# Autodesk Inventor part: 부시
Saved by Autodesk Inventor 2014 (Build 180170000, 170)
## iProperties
Created: 2026-09
Part Number: 부시
Material: 일반
Document SubType Name: Modeling
Designer: dg
Density: 1 g/cm^3
Appearance: 기본값
Author: dg
Author: jhkim
Creation Date: 2026-08-27
Sending System: Autodesk Inventor 2027
Preprocessor: ST-DEVELOPER v20.1
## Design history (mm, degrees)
node "부시1"
node "솔리드1"
node "기준1"
